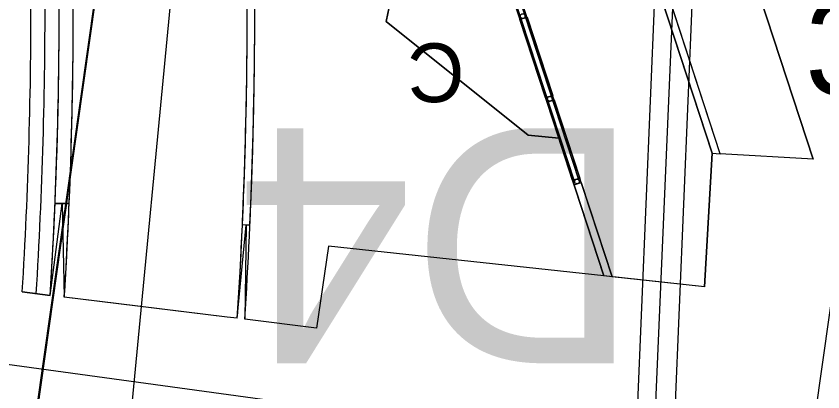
# Model space of a CAD drawing. Extents: x -728800 to -728100, y -1073200 to -1072700.
# Drawn here: x -728502.23 to -728493.65, y -1073043.53 to -1073039.54 of the extents above; entities that cross this region are included whole.
import ezdxf

# ---------------------------------------------------------------- set-up
doc = ezdxf.new("R2010")
doc.units = 0
for name, color, linetype in [('_NOR-návrh tenká', 7, 'Continuous'), ('_NOR-VDZ', 7, 'Continuous'), ('_NOR-šraf_+-0', 7, 'Continuous'), ('_NOR-šraf_+12', 7, 'Continuous'), ('_NOR-šraf_+6', 7, 'Continuous'), ('_NOR-šraf_chodník', 7, 'Continuous'), ('_NOR-šraf_vozovka', 7, 'Continuous'), ('_NOR-šraf_zeleň', 7, 'Continuous'), ('A1_OBVOD Spravy železnic', 7, 'Continuous'), ('B2_body_číslo', 7, 'Continuous'), ('B6_JŽM', 7, 'Continuous'), ('K_01_Hranice parcel', 7, 'Continuous'), ('KOS_kabelová trasa', 7, 'Continuous'), ('KOS_nové prvky PZZ', 7, 'Continuous'), ('ZA_01_Trvalý_pro_SŽDC_dle_UMVZST', 7, 'Continuous'), ('ZA_02_Dočasný_do_1_roku', 7, 'Continuous')]:
    doc.layers.add(name, color=color, linetype=linetype)

msp = doc.modelspace()

# ---------------------------------------------------------------- linework, layer by layer
at = {"layer": '_NOR-návrh tenká'}
for p, q in [((-728494.83, -1073040.995), (-728496.6299, -1073035.4928)), ((-728494.7442, -1073041.0001), (-728496.5539, -1073035.4679)), ((-728495.9818, -1073042.2985), (-728498.0556, -1073035.9592)), ((-728495.8946, -1073042.3079), (-728497.9796, -1073035.9343)), ((-728496.2444, -1073041.2869), (-728497.97, -1073036.0119)), ((-728496.2919, -1073041.3024), (-728498.0175, -1073036.0275)), ((-728493.7572, -1073041.0582), (-728495.3935, -1073036.0563)), ((-728501.4824, -1073048.6764), (-728500.3754, -1073037.1911)), ((-728494.91, -1073042.414), (-728494.83, -1073040.995)), ((-728501.8676, -1073042.5064), (-728501.7419, -1073041.5296)), ((-728501.8169, -1073041.5296), (-728501.6668, -1073041.5296)), ((-728501.7419, -1073041.5296), (-728501.7184, -1073042.5247)), ((-728499.8789, -1073042.7498), (-728499.785, -1073041.7592)), ((-728499.745, -1073041.761), (-728499.825, -1073041.7574)), ((-728499.785, -1073041.7592), (-728499.7994, -1073042.7595)), ((-728494.91, -1073042.414), (-728495.9818, -1073042.2985))]:
    msp.add_line(p, q, dxfattribs=at)
msp.add_lwpolyline([(-728502.1659, -1073042.4699), (-728501.8676, -1073042.5064)], dxfattribs=at)
for centre in [(-728496.8433, -1073039.5363), (-728496.5557, -1073040.4155), (-728496.2681, -1073041.2946)]:
    msp.add_circle(centre, 0.025, dxfattribs=at)
for radius, start in [(49.7, 356.49472), (50, 356.47386), (50.15, 356.46353), (52, 356.34097), (52.08, 356.33586)]:
    msp.add_arc((-728551.7729, -1073039.4312), radius, start, 0.20859, dxfattribs=at)
at = {"layer": '_NOR-VDZ'}
msp.add_arc((-728551.7729, -1073039.4312), 49.85, 356.48426, 0.20859, dxfattribs=at)
at = {"layer": '_NOR-šraf_+-0'}
msp.add_lwpolyline([(-728494.83, -1073040.995), (-728494.7442, -1073041.0001), (-728496.5539, -1073035.4679), (-728496.6299, -1073035.4928), (-728494.83, -1073040.995), (-728494.83, -1073040.995)], dxfattribs=at)
at = {"layer": '_NOR-šraf_+12'}
msp.add_lwpolyline([(-728501.6668, -1073041.5296), (-728501.7419, -1073041.5296), (-728501.8169, -1073041.5296)], dxfattribs=at)
for radius, start in [(50, 357.5948), (50.15, 357.602)]:
    msp.add_arc((-728551.7729, -1073039.4312), radius, start, 0.20859, dxfattribs=at)
at = {"layer": '_NOR-šraf_+6'}
for p, q in [((-728496.8736, -1073039.5725), (-728496.7975, -1073039.5476)), ((-728496.6015, -1073040.4041), (-728496.8736, -1073039.5725)), ((-728496.7975, -1073039.5476), (-728496.5255, -1073040.3793)), ((-728496.5255, -1073040.3793), (-728496.6015, -1073040.4041)), ((-728496.586, -1073040.4517), (-728496.5099, -1073040.4268)), ((-728496.3139, -1073041.2833), (-728496.586, -1073040.4517)), ((-728496.5099, -1073040.4268), (-728496.2379, -1073041.2584)), ((-728496.2379, -1073041.2584), (-728496.3139, -1073041.2833)), ((-728496.2984, -1073041.3308), (-728496.2223, -1073041.3059)), ((-728495.9818, -1073042.2985), (-728496.2984, -1073041.3308)), ((-728496.2223, -1073041.3059), (-728495.8946, -1073042.3079)), ((-728499.785, -1073041.7592), (-728499.825, -1073041.7574)), ((-728499.745, -1073041.761), (-728499.785, -1073041.7592)), ((-728495.8946, -1073042.3079), (-728495.9818, -1073042.2985))]:
    msp.add_line(p, q, dxfattribs=at)
msp.add_lwpolyline([(-728499.745, -1073041.761), (-728499.785, -1073041.7592), (-728499.825, -1073041.7574)], dxfattribs=at)
for centre, radius, start, end in [((-728551.7729, -1073039.4312), 52, 357.43603, 0.20859), ((-728551.7729, -1073039.4312), 52.08, 357.43603, 0.20859), ((-728551.7725, -1073039.4312), 51.9996, 359.87159, 359.92959), ((-728551.7729, -1073039.4312), 52.08, 358.88417, 359.9006), ((-728551.7729, -1073039.4312), 52, 358.85342, 359.87159), ((-728551.7732, -1073039.4312), 52.0004, 358.79505, 358.85342), ((-728551.7727, -1073039.4312), 52.0798, 358.8259, 358.88417), ((-728551.7729, -1073039.4312), 52, 357.77014, 358.79505), ((-728551.7729, -1073039.4312), 52.08, 357.80277, 358.8259), ((-728551.7732, -1073039.4312), 52.0003, 357.71137, 357.77014), ((-728551.7729, -1073039.4312), 52.08, 357.43603, 357.7441), ((-728551.7726, -1073039.4313), 52.0797, 357.7441, 357.80277), ((-728551.7729, -1073039.4312), 52, 357.43603, 357.71137)]:
    msp.add_arc(centre, radius, start, end, dxfattribs=at)
at = {"layer": '_NOR-šraf_chodník'}
for p, q in [((-728496.6472, -1073035.44), (-728494.83, -1073040.995)), ((-728495.8946, -1073042.3079), (-728497.9906, -1073035.9006)), ((-728494.83, -1073040.995), (-728494.91, -1073042.414)), ((-728494.91, -1073042.414), (-728495.8946, -1073042.3079)), ((-728499.9874, -1073042.7365), (-728501.7184, -1073042.5247)), ((-728499.8789, -1073042.7498), (-728499.9874, -1073042.7365))]:
    msp.add_line(p, q, dxfattribs=at)
msp.add_lwpolyline([(-728499.8789, -1073042.7498), (-728499.9874, -1073042.7365), (-728501.1678, -1073042.5921), (-728501.7184, -1073042.5247)], dxfattribs=at)
for radius, start, end in [(50.15, 356.46353, 0.20859), (50.15, 357.602, 0.20859), (52, 356.34097, 0.20859), (52, 357.43603, 0.20859), (50.15, 356.46353, 357.602), (52, 356.34097, 357.43603)]:
    msp.add_arc((-728551.7729, -1073039.4312), radius, start, end, dxfattribs=at)
at = {"layer": '_NOR-šraf_vozovka'}
msp.add_lwpolyline([(-728501.8676, -1073042.5064), (-728502.1659, -1073042.4699)], dxfattribs=at)
for radius, start, end in [(49.7, 356.49472, 0.20859), (50, 357.5948, 0.20859), (50, 356.47386, 357.5948)]:
    msp.add_arc((-728551.7729, -1073039.4312), radius, start, end, dxfattribs=at)
at = {"layer": '_NOR-šraf_zeleň'}
for p, q in [((-728494.7442, -1073041.0001), (-728496.5539, -1073035.4679)), ((-728495.3935, -1073036.0563), (-728493.7572, -1073041.0582)), ((-728497.8284, -1073037.3593), (-728498.297, -1073039.593)), ((-728498.297, -1073039.593), (-728496.785, -1073040.803)), ((-728496.785, -1073040.803), (-728496.4606, -1073040.8349)), ((-728496.4606, -1073040.8349), (-728495.9818, -1073042.2985)), ((-728493.7572, -1073041.0582), (-728494.7442, -1073041.0001)), ((-728498.908, -1073041.983), (-728499.0357, -1073042.853)), ((-728495.9818, -1073042.2985), (-728498.908, -1073041.983)), ((-728499.0357, -1073042.853), (-728499.7994, -1073042.7595))]:
    msp.add_line(p, q, dxfattribs=at)
msp.add_lwpolyline([(-728496.4606, -1073040.8349), (-728496.785, -1073040.803), (-728498.297, -1073039.593), (-728497.8284, -1073037.3593), (-728497.826, -1073037.348), (-728497.7942, -1073037.3251), (-728497.6441, -1073037.217), (-728496.4606, -1073040.8349)], dxfattribs=at)
msp.add_arc((-728551.7729, -1073039.4312), 52.08, 356.33586, 0.20859, dxfattribs=at)
at = {"layer": 'A1_OBVOD Spravy železnic'}
msp.add_lwpolyline([(-728503.24, -1073052.34), (-728501.19, -1073037.94), (-728499.78, -1073032.61), (-728497.54, -1073030.15), (-728493.68, -1073027.94), (-728443.97, -1073014.59), (-728443.68, -1073014.51), (-728441.09, -1073023.23), (-728428.92, -1073019.94), (-728429.82, -1073016.43), (-728427.49, -1073015.84), (-728421.24, -1073014.23), (-728422.34, -1073010.27), (-728422.77, -1073008.34), (-728418.21, -1073007), (-728380.57, -1072997.2), (-728343.1, -1072987.57), (-728330.49, -1072984.52), (-728326.79, -1072988.95)], dxfattribs=at)
at = {"layer": 'B6_JŽM'}
msp.add_lwpolyline([(-728300.8085, -1073024.3545), (-728320.8, -1073026.914), (-728374.008, -1073033.722), (-728429.095, -1073040.747), (-728461.932, -1073044.273), (-728481.199, -1073044.815), (-728499.353, -1073043.648), (-728506.01, -1073042.737), (-728514.574, -1073041.329), (-728535.848, -1073035.998), (-728561.353, -1073026.113), (-728583.963, -1073013.524), (-728603.757, -1072998.891), (-728619.185, -1072984.418), (-728634.193, -1072966.825), (-728646.078, -1072949.194), (-728656.182, -1072930.072), (-728664.987, -1072910.227), (-728668.627, -1072901.808), (-728681.252, -1072876.016), (-728691.886, -1072859.663)], dxfattribs=at)
at = {"layer": 'K_01_Hranice parcel'}
msp.add_line((-728501.19, -1073037.94), (-728502.6, -1073047.92), dxfattribs=at)
at = {"layer": 'KOS_kabelová trasa'}
for p, q in [((-728495.7665, -1073047.15), (-728495.3938, -1073038.2172)), ((-728495.3669, -1073047.1667), (-728494.9941, -1073038.2339))]:
    msp.add_line(p, q, dxfattribs=at)
msp.add_lwpolyline([(-728499.6877, -1073048.4364), (-728495.6152, -1073048.0137), (-728495.1842, -1073037.964)], dxfattribs=at)
at = {"layer": 'ZA_01_Trvalý_pro_SŽDC_dle_UMVZST'}
msp.add_lwpolyline([(-728502.83, -1073049.48), (-728501.19, -1073037.94), (-728500.7194, -1073036.1609), (-728510.3267, -1073035.4653), (-728510.22, -1073036.28), (-728509.42, -1073042.19), (-728509.9, -1073046.86), (-728517.0095, -1073045.1202), (-728517.3822, -1073047.3107), (-728510.2456, -1073048.3747)], dxfattribs=at)
at = {"layer": 'ZA_02_Dočasný_do_1_roku'}
for points in [[(-728493.51, -1073034.35), (-728493.84, -1073039.37), (-728501.19, -1073037.94), (-728502.0422, -1073043.9717)], [(-728494.1165, -1073046.4898), (-728493.3495, -1073041.0682)]]:
    msp.add_lwpolyline(points, dxfattribs=at)

# ---------------------------------------------------------------- texts
at = {"layer": 'B2_body_číslo'}
msp.add_text('31', height=1, dxfattribs=at).set_placement((-728493.84, -1073040.37))
at = {"layer": 'KOS_nové prvky PZZ'}
msp.add_text('C', height=0.625, rotation=180, dxfattribs=at).set_placement((-728497.4635, -1073039.8255))
at = {"layer": 'ZA_02_Dočasný_do_1_roku'}
msp.add_text('D4', height=2.5, rotation=180, dxfattribs=at).set_placement((-728495.6037, -1073040.728))

doc.saveas('drawing.dxf')
